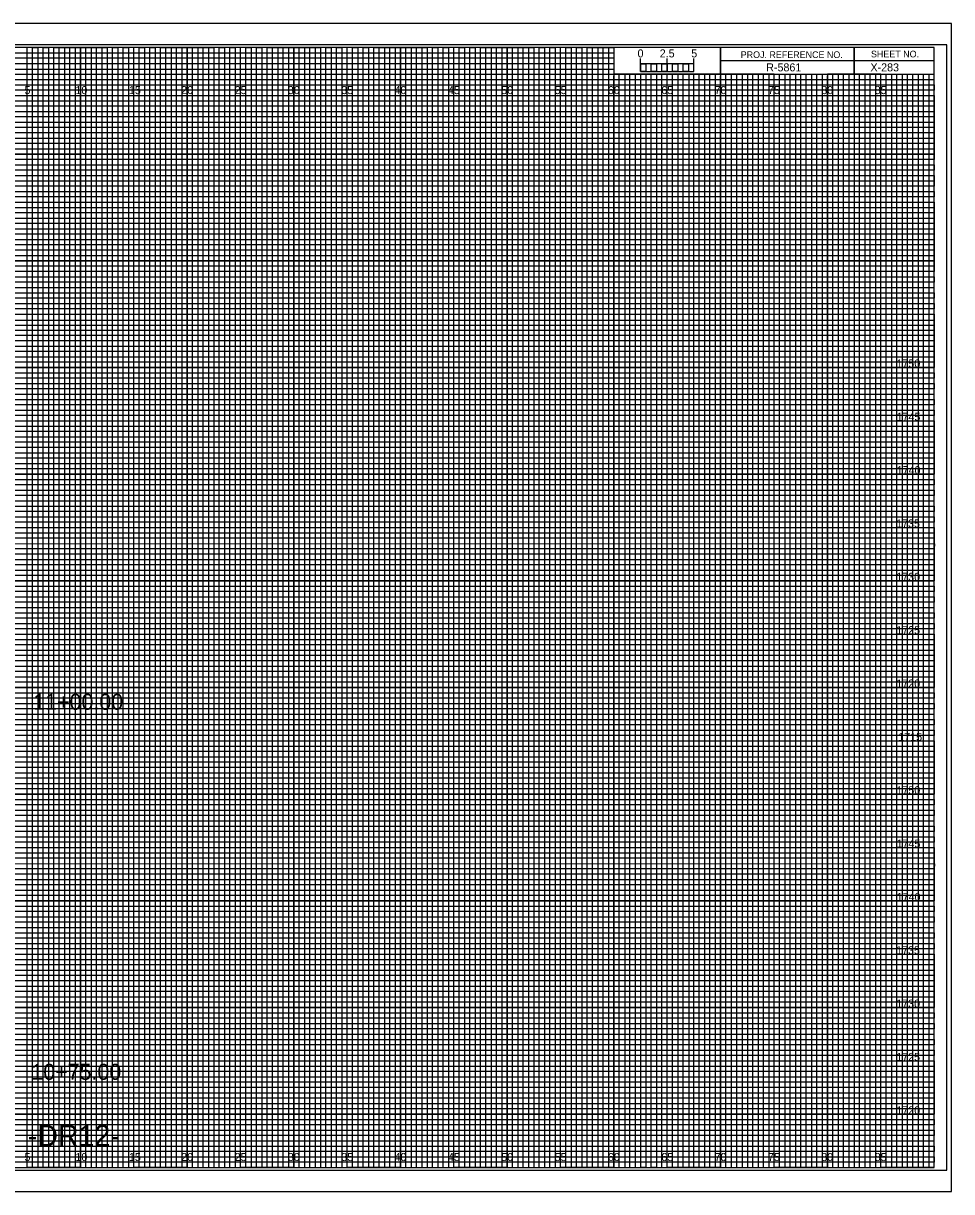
# Model space of a CAD drawing. Extents: x -7 to 162, y -2 to 327.
# Drawn here: x 74.6 to 161.7, y 107.7 to 217.2 of the extents above; entities that cross this region are included whole.
import ezdxf

# ---------------------------------------------------------------- set-up
doc = ezdxf.new("R2010")
doc.units = 0
for name, color, linetype in [('Prop XS Alignment Label', 7, 'Continuous'), ('Prop XS Bar Scale Labels', 7, 'Continuous'), ('Prop XS Elevation Labels', 7, 'Continuous'), ('Prop XS Offset Labels', 7, 'Continuous'), ('Prop XS Project Number', 7, 'Continuous'), ('Prop XS Sheet Number', 7, 'Continuous'), ('Prop XS Station Labels', 7, 'Continuous'), ('Sheet Cross Section CELL', 7, 'Continuous'), ('Sheet Cross Section Grid Major CELL', 7, 'Continuous'), ('Sheet Cross Section Grid Middle CELL', 7, 'Continuous'), ('Sheet Cross Section Grid Minor 1 CELL', 7, 'Continuous'), ('Sheet Cross Section Grid Minor 2 CELL', 7, 'Continuous'), ('Sheet Cross Section Scale CELL', 7, 'Continuous'), ('Sheet Cutting Line CELL', 7, 'Continuous'), ('Sheet DOT Grid CELL', 7, 'Continuous'), ('Sheet Plot Border Inside CELL', 7, 'Continuous'), ('Sheet Plot Border Outside CELL', 7, 'Continuous')]:
    doc.layers.add(name, color=color, linetype=linetype)

msp = doc.modelspace()

# ---------------------------------------------------------------- linework, layer by layer
at = {"layer": 'Sheet Cross Section CELL'}
for p, q in [((152.5, 215), (152.5, 212.5)), ((152.5, 212.5), (152.5, 215)), ((160, 213.75), (140, 213.75)), ((140, 213.75), (140, 212.5)), ((140, 212.5), (160, 212.5))]:
    msp.add_line(p, q, dxfattribs=at)
for points in [[(160, 215), (0, 215), (0, 110), (160, 110)], [(140, 215), (130, 215), (130, 212.52), (140, 212.52)], [(160, 215), (140, 215), (140, 212.5), (160, 212.5)]]:
    msp.add_lwpolyline(points, close=True, dxfattribs=at)
at = {"layer": 'Sheet Cross Section Grid Major CELL'}
for p, q in [((75, 215), (70, 215)), ((75, 110), (75, 215)), ((85, 215), (80, 215)), ((80, 215), (80, 110)), ((85, 110), (85, 215)), ((95, 215), (90, 215)), ((90, 215), (90, 110)), ((95, 110), (95, 215)), ((105, 215), (100, 215)), ((100, 215), (100, 110)), ((105, 110), (105, 215)), ((115, 215), (110, 215)), ((110, 215), (110, 110)), ((115, 110), (115, 215)), ((125, 215), (120, 215)), ((120, 215), (120, 110)), ((125, 110), (125, 215)), ((130, 215), (130, 110)), ((135, 110), (135, 212.5)), ((145, 212.5), (140, 212.5)), ((140, 212.5), (140, 110)), ((145, 110), (145, 212.5)), ((155, 212.5), (150, 212.5)), ((150, 212.5), (150, 110)), ((155, 110), (155, 212.5)), ((80, 110), (75, 110)), ((90, 110), (85, 110)), ((100, 110), (95, 110)), ((110, 110), (105, 110)), ((120, 110), (115, 110)), ((130, 110), (125, 110)), ((140, 110), (135, 110)), ((150, 110), (145, 110)), ((160, 110), (155, 110)), ((160, 110), (160, 110))]:
    msp.add_line(p, q, dxfattribs=at)
for points in [[(0, 210), (160, 210), (160, 205), (0, 205)], [(0, 200), (160, 200), (160, 195), (0, 195)], [(0, 190), (160, 190), (160, 185), (0, 185)], [(0, 180), (160, 180), (160, 175), (0, 175)], [(0, 170), (160, 170), (160, 165), (0, 165)], [(0, 160), (160, 160), (160, 155), (0, 155)], [(0, 150), (160, 150), (160, 145), (0, 145)], [(0, 140), (160, 140), (160, 135), (0, 135)], [(0, 130), (160, 130), (160, 125), (0, 125)], [(0, 120), (160, 120), (160, 115), (0, 115)]]:
    msp.add_lwpolyline(points, dxfattribs=at)
at = {"layer": 'Sheet Cross Section Grid Middle CELL'}
for points in [[(72.5, 110), (77.5, 110), (77.5, 215), (82.5, 215), (82.5, 110), (87.5, 110), (87.5, 215), (92.5, 215), (92.5, 110), (97.5, 110), (97.5, 215), (102.5, 215), (102.5, 110), (107.5, 110), (107.5, 215), (112.5, 215), (112.5, 110), (117.5, 110), (117.5, 215), (122.5, 215), (122.5, 110), (127.5, 110), (127.5, 215), (129.97, 215), (130, 215), (130, 212.5), (132.5, 212.5), (132.5, 110), (137.5, 110), (137.5, 212.5), (142.5, 212.5), (142.5, 110), (147.5, 110), (147.5, 212.5), (152.5, 212.5), (152.5, 110), (157.5, 110), (157.5, 212.5)], [(0, 212.5), (137.5, 212.5)], [(0, 202.5), (160, 202.5), (160, 207.5), (0, 207.5)], [(0, 192.5), (160, 192.5), (160, 197.5), (0, 197.5)], [(0, 182.5), (160, 182.5), (160, 187.5), (0, 187.5)], [(0, 172.5), (160, 172.5), (160, 177.5), (0, 177.5)], [(0, 162.5), (160, 162.5), (160, 167.5), (0, 167.5)], [(0, 152.5), (160, 152.5), (160, 157.5), (0, 157.5)], [(0, 142.5), (160, 142.5), (160, 147.5), (0, 147.5)], [(0, 132.5), (160, 132.5), (160, 137.5), (0, 137.5)], [(0, 122.5), (160, 122.5), (160, 127.5), (0, 127.5)], [(0, 112.5), (160, 112.5), (160, 117.5), (0, 117.5)]]:
    msp.add_lwpolyline(points, dxfattribs=at)
at = {"layer": 'Sheet Cross Section Grid Minor 1 CELL'}
for p, q in [((0, 214.5), (130, 214.5)), ((130, 213.99), (0, 213.99)), ((130, 214.5), (130, 213.99)), ((0, 213.5), (130, 213.5)), ((130, 212.94), (0, 212.94)), ((130, 213.5), (130, 212.94)), ((0, 212), (160, 212))]:
    msp.add_line(p, q, dxfattribs=at)
for points in [[(0, 211.5), (135, 211.5), (160, 211.5), (160, 211), (0, 211)], [(0, 210.5), (160, 210.5), (160, 209.5), (0, 209.5)], [(0, 209), (160, 209), (160, 208.5), (0, 208.49)], [(0, 208), (160, 208), (160, 207), (0, 207)], [(0, 206.5), (160, 206.5), (160, 206), (0, 206)], [(0, 205.5), (160, 205.5), (160, 204.5), (0, 204.5)], [(0, 204), (160, 204), (160, 203.5), (0, 203.5)], [(0, 203), (160, 203), (160, 202), (0, 202)], [(0, 201.5), (160, 201.5), (160, 201), (0, 201)], [(0, 200.5), (160, 200.5), (160, 199.5), (0, 199.5)], [(0, 199), (160, 199), (160, 198.5), (0, 198.5)], [(0, 198), (160, 198), (160, 196.97), (160, 196.5), (160, 196), (0, 196)], [(0, 197), (160, 197), (160, 196.5), (0, 196.5)], [(0, 195.5), (160, 195.5), (160, 194.5), (0, 194.52)], [(0, 194.52), (160, 194.5), (160, 194), (0, 194)], [(0, 193.5), (160, 193.5), (160, 193), (0, 193)], [(0, 192), (160, 192), (160, 191.5), (0, 191.5)], [(0, 191), (160, 191), (160, 190.5), (0, 190.5)], [(-0.04, 189.44), (160, 189.44), (160, 188.94), (-0.04, 188.94)], [(0, 188.5), (160, 188.5), (160, 188), (0, 188)], [(0, 187), (160, 187), (160, 186.5), (0, 186.5)], [(0, 186), (160, 186), (160, 185.5), (0, 185.5)], [(0, 184.5), (160, 184.5), (160, 184), (0, 184)], [(0, 183.5), (160, 183.5), (160, 183), (0, 183)], [(0, 182), (160, 182), (160, 181.5), (0, 181.5)], [(0, 181), (160, 181), (160, 180.5), (0, 180.5)], [(0, 179.5), (160, 179.5), (160, 178.99), (0, 179)], [(0, 178.5), (160, 178.5), (160, 178), (0, 178)], [(0, 177), (160, 177), (160, 176.5), (0, 176.5)], [(0, 176), (160, 176), (160, 175.5), (0, 175.5)], [(0, 174.5), (160, 174.5), (160, 174), (0, 174)], [(0, 173.5), (160, 173.5), (160, 173), (0, 173)], [(0, 172), (160, 172), (160, 171.5), (0, 171.5)], [(0, 171), (160, 171), (160, 170.5), (0, 170.5)], [(0, 169.5), (160, 169.5), (160, 169), (0, 169)], [(0, 168.5), (160.03, 168.46), (160, 168), (0, 168)], [(0, 167), (160, 167), (160, 166.5), (0, 166.5)], [(0, 166), (160, 166), (160, 165.5), (0, 165.5)], [(0, 164.5), (160, 164.5), (160, 164), (0, 164)], [(0, 163.5), (160, 163.5), (160, 163), (0, 163)], [(0, 162), (160, 162), (160, 161.5), (0, 161.5)], [(0, 161), (160, 161), (160, 160.5), (0, 160.5)], [(0, 159.5), (160, 159.5), (160, 159), (0, 159)], [(0, 158.5), (160, 158.5), (160, 158), (0, 158)], [(0, 157), (160, 157), (160, 156.5), (0, 156.5)], [(0, 156), (160, 156), (160, 155.5), (0, 155.5)], [(0, 154.5), (160, 154.5), (160, 154), (0, 154)], [(0, 153.5), (160, 153.5), (160, 153), (0, 153)], [(0, 152), (160, 152), (160, 151.5), (0, 151.5)], [(0, 151), (160, 151), (160, 150.5), (0, 150.5)], [(0, 149.5), (160, 149.5), (160, 148.99), (0, 149)], [(0, 148.5), (160, 148.5), (160, 148), (0, 148)], [(0, 147), (160, 147), (160, 146.5), (0, 146.5)], [(0, 146), (160, 146), (160, 145.5), (0, 145.5)], [(0, 144.5), (160, 144.5), (160, 144), (0, 144)], [(0, 143.5), (160, 143.5), (160, 143), (0, 143)], [(0, 142), (160, 142), (160, 141.5), (0, 141.5)], [(0, 141), (160, 141), (160, 140.5), (0, 140.5)], [(0, 139.5), (160, 139.5), (160, 139), (0, 139)], [(0, 138.5), (160.03, 138.46), (160, 138), (0, 138)], [(0, 137), (160, 137), (160, 136.5), (0, 136.5)], [(0, 136), (160, 136), (160, 135.5), (0, 135.5)], [(0, 134.5), (160, 134.5), (160, 134), (0, 134)], [(0, 133.5), (160, 133.5), (160, 133), (0, 133)], [(0, 132), (160, 132), (160, 131.5), (0, 131.5)], [(0, 131), (160, 131), (160, 130.5), (0, 130.5)], [(0, 129.5), (160, 129.5), (160, 129), (0, 129)], [(0, 128.5), (160, 128.5), (160, 128), (0, 128)], [(0, 127), (160, 127), (160, 126.5), (0, 126.5)], [(0, 126), (160, 126), (160, 125.5), (0, 125.5)], [(0, 124.5), (160, 124.5), (160, 124), (0, 124)], [(0, 123.5), (160, 123.5), (160, 123), (0, 123)], [(0, 122), (160, 122), (160, 121.5), (0, 121.5)], [(0, 121), (160, 121), (160, 120.5), (0, 120.5)], [(0, 119.5), (160, 119.5), (160, 119), (0, 119)], [(0, 118.5), (160, 118.5), (160, 118), (0, 118)], [(0, 117), (160, 117), (160, 116.5), (0, 116.5)], [(0, 116), (160, 116), (160, 115.5), (0, 115.5)], [(0, 114.5), (160, 114.5), (160, 114), (0, 114)], [(0, 113.5), (160, 113.5), (160, 113), (0, 113)], [(0, 112), (160, 112), (160, 111.5), (0, 111.5)], [(0, 111), (160, 111), (160, 110.5), (0, 110.5)]]:
    msp.add_lwpolyline(points, dxfattribs=at)
at = {"layer": 'Sheet Cross Section Grid Minor 2 CELL'}
for p, q in [((133.5, 212.5), (133, 212.5)), ((133, 212.5), (133, 110)), ((133.5, 110), (133.5, 212.5)), ((134.5, 212.5), (134, 212.5)), ((134, 212.5), (134, 110)), ((134.5, 110), (134.5, 212.5)), ((133, 110), (132.5, 110)), ((134, 110), (133.5, 110))]:
    msp.add_line(p, q, dxfattribs=at)
for points in [[(75, 110), (75.5, 110), (75.5, 215), (76, 215), (76, 110)], [(76, 110), (76.5, 110), (76.5, 215), (77, 215), (77, 110)], [(77.5, 110), (78, 110), (78, 215), (78.5, 215), (78.5, 110)], [(78.5, 110), (79, 110), (79, 215), (79.5, 215), (79.5, 110)], [(80, 110), (80.5, 110), (80.5, 215), (81, 215), (81, 110)], [(81, 110), (81.5, 110), (81.5, 215), (82, 215), (82, 110)], [(82.5, 110), (83, 110), (83, 215), (83.5, 215), (83.5, 110)], [(83.5, 110), (84, 110), (84, 215), (84.5, 215), (84.5, 110)], [(85, 110), (85.5, 110), (85.5, 215), (86, 215), (86, 110)], [(86, 110), (86.5, 110), (86.5, 215), (87, 215), (87, 110)], [(87.5, 110), (88, 110), (88, 215), (88.5, 215), (88.5, 110)], [(88.5, 110), (89, 110), (89, 215), (89.5, 215), (89.5, 110)], [(90, 110), (90.5, 110), (90.5, 215), (91, 215), (91, 110)], [(91, 110), (91.5, 110), (91.5, 215), (92, 215), (92, 110)], [(92.5, 110), (93, 110), (93, 215), (93.5, 215), (93.5, 110)], [(93.5, 110), (94, 110), (94, 215), (94.5, 215), (94.5, 110)], [(95, 110), (95.5, 110), (95.5, 215), (96, 215), (96, 110)], [(96, 110), (96.5, 110), (96.5, 215), (97, 215), (97, 110)], [(97.5, 110), (98, 110), (98, 215), (98.5, 215), (98.5, 110)], [(98.5, 110), (99, 110), (99, 215), (99.5, 215), (99.5, 110)], [(100, 110), (100.5, 110), (100.5, 215), (101, 215), (101, 110)], [(101, 110), (101.5, 110), (101.5, 215), (102, 215), (102, 110)], [(102.5, 110), (103, 110), (103, 215), (103.5, 215), (103.5, 110)], [(103.5, 110), (104, 110), (104, 215), (104.5, 215), (104.5, 110)], [(105, 110), (105.5, 110), (105.5, 215), (106, 215), (106, 110)], [(106, 110), (106.5, 110), (106.5, 215), (107, 215), (107, 110)], [(107.5, 110), (108, 110), (108, 215), (108.5, 215), (108.5, 110)], [(108.5, 110), (109, 110), (109, 215), (109.5, 215), (109.5, 110)], [(110, 110), (110.5, 110), (110.5, 215), (111, 215), (111, 110)], [(111, 110), (111.5, 110), (111.5, 215), (112, 215), (112, 110)], [(112.5, 110), (113, 110), (113, 215), (113.5, 215), (113.5, 110)], [(113.5, 110), (114, 110), (114, 215), (114.5, 215), (114.5, 110)], [(115, 110), (115.5, 110), (115.5, 215), (116, 215), (116, 110)], [(116, 110), (116.5, 110), (116.5, 215), (117, 215), (117, 110)], [(117.5, 110), (118, 110), (118, 215), (118.5, 215), (118.5, 110)], [(118.5, 110), (119, 110), (119, 215), (119.5, 215), (119.5, 110)], [(120, 110), (120.5, 110), (120.5, 215), (121, 215), (121, 110)], [(121, 110), (121.5, 110), (121.5, 215), (122, 215), (122, 110)], [(122.5, 110), (123, 110), (123, 215), (123.5, 215), (123.5, 110)], [(123.5, 110), (124, 110), (124, 215), (124.5, 215), (124.5, 110)], [(125, 110), (125.5, 110), (125.5, 215), (126, 215), (126, 110)], [(126, 110), (126.5, 110), (126.5, 215), (127, 215), (127, 110)], [(127.5, 110), (128, 110), (128, 215), (128.5, 215), (128.5, 110)], [(128.5, 110), (129, 110), (129, 215), (129.5, 215), (129.5, 110)], [(130, 110), (130.5, 110), (130.5, 212.5), (131.01, 212.5), (131.01, 110)], [(131, 110), (131.5, 110), (131.5, 212.5), (132, 212.5), (132, 110)], [(135, 110), (135.49, 110), (135.49, 212.5), (136, 212.5), (136, 110)], [(136, 110), (136.5, 110), (136.5, 212.5), (137.03, 212.5), (137.03, 110)], [(137.5, 110), (138, 110), (138, 212.5), (138.5, 212.5), (138.5, 110)], [(138.5, 110), (139, 110), (139, 212.5), (139.5, 212.5), (139.5, 110)], [(140, 110), (140.5, 110), (140.5, 212.5), (141, 212.5), (141, 110)], [(141, 110), (141.5, 110), (141.5, 212.5), (142, 212.5), (142, 110)], [(142.5, 110), (143, 110), (143, 212.5), (143.5, 212.5), (143.5, 110)], [(143.5, 110), (144, 110), (144, 212.5), (144.5, 212.5), (144.5, 110)], [(145, 110), (145.5, 110), (145.5, 212.5), (146, 212.5), (146, 110)], [(146, 110), (146.5, 110), (146.5, 212.5), (147, 212.5), (147, 110)], [(147.5, 110), (148, 110), (148, 212.5), (148.5, 212.5), (148.5, 110)], [(148.5, 110), (149, 110), (149, 212.5), (149.5, 212.5), (149.5, 110)], [(150, 110), (150.5, 110), (150.5, 212.5), (151, 212.5), (151, 110)], [(151, 110), (151.5, 110), (151.5, 212.5), (152, 212.5), (152, 110)], [(152.5, 110), (153, 110), (153, 212.5), (153.5, 212.5), (153.5, 110)], [(153.5, 110), (154, 110), (154, 212.5), (154.5, 212.5), (154.5, 110)], [(155, 110), (155.5, 110), (155.5, 212.5), (156, 212.5), (156, 110)], [(156, 110), (156.5, 110), (156.5, 212.5), (157, 212.5), (157, 110)], [(157.5, 110), (158, 110), (158, 212.5), (158.5, 212.5), (158.5, 110)], [(158.5, 110), (159, 110), (159, 212.5), (159.5, 212.5), (159.5, 110)]]:
    msp.add_lwpolyline(points, dxfattribs=at)
at = {"layer": 'Sheet Cross Section Scale CELL'}
for p, q in [((132.5, 212.75), (132.5, 213.95)), ((132.5, 213.45), (132.5, 213.95)), ((135, 212.75), (135, 213.95)), ((137.5, 212.75), (137.5, 213.95)), ((137.5, 213.45), (137.5, 213.95))]:
    msp.add_line(p, q, dxfattribs=at)
for points in [[(137.5, 213.45), (132.5, 213.45), (132.5, 212.75), (137.5, 212.75)], [(132.5, 213.45), (133, 213.45), (133, 212.75), (132.5, 212.75)], [(133.5, 213.45), (134, 213.45), (134, 212.75), (133.5, 212.75)], [(134.5, 213.45), (135, 213.45), (135, 212.75), (134.5, 212.75)], [(135.5, 213.45), (136, 213.45), (136, 212.75), (135.5, 212.75)], [(136.5, 213.45), (137, 213.45), (137, 212.75), (136.5, 212.75)]]:
    msp.add_lwpolyline(points, close=True, dxfattribs=at)
at = {"layer": 'Sheet Cutting Line CELL'}
for p, q in [((161.65, 217.25), (-6.7, 217.25)), ((-6.7, 107.75), (161.65, 107.75))]:
    msp.add_line(p, q, dxfattribs=at)
at = {"layer": 'Sheet DOT Grid CELL'}
for p, q in [((75, 110), (75, 215)), ((80, 110), (80, 215)), ((85, 110), (85, 215)), ((90, 110), (90, 215)), ((95, 110), (95, 215)), ((100, 110), (100, 215)), ((105, 110), (105, 215)), ((110, 110), (110, 215)), ((115, 110), (115, 215)), ((120, 110), (120, 215)), ((125, 110), (125, 215)), ((130, 110), (130, 212.34)), ((135, 110), (135, 212.34)), ((140, 110), (140, 212.34)), ((145, 110), (145, 212.34)), ((150, 110), (150, 212.34)), ((155, 110), (155, 212.34)), ((0, 210), (160, 210)), ((0, 205), (160, 205)), ((0, 200), (160, 200)), ((0, 195), (160, 195)), ((0, 190), (160, 190)), ((0, 185), (160, 185)), ((0, 180), (160, 180)), ((0, 175), (160, 175)), ((0, 170), (160, 170)), ((0, 165), (160, 165)), ((0, 160), (160, 160)), ((0, 155), (160, 155)), ((0, 150), (160, 150)), ((0, 145), (160, 145)), ((0, 140), (160, 140)), ((0, 135), (160, 135)), ((0, 130), (160, 130)), ((0, 125), (160, 125)), ((0, 120), (160, 120)), ((0, 115), (160, 115))]:
    msp.add_line(p, q, dxfattribs=at)
at = {"layer": 'Sheet Plot Border Inside CELL'}
msp.add_lwpolyline([(-5.4, 109.75), (161.2, 109.75), (161.2, 215.25), (-5.4, 215.25)], close=True, dxfattribs=at)
at = {"layer": 'Sheet Plot Border Outside CELL'}
msp.add_lwpolyline([(-6.7, 107.75), (161.65, 107.75), (161.65, 217.25), (-6.7, 217.25)], close=True, dxfattribs=at)

# ---------------------------------------------------------------- texts
at = {"layer": 'Prop XS Alignment Label'}
msp.add_text('-DR12-', height=2, dxfattribs=at).set_placement((75.06, 112))
at = {"layer": 'Prop XS Bar Scale Labels'}
for s, p in [('2.5', (134.29, 214.06)), ('5', (137.24, 214.06))]:
    msp.add_text(s, height=0.75, dxfattribs=at).set_placement(p)
at = {"layer": 'Prop XS Elevation Labels'}
for s, p in [('1750', (156.48, 185)), ('1745', (156.49, 180)), ('1740', (156.5, 175)), ('1735', (156.45, 170)), ('1730', (156.46, 165)), ('1725', (156.46, 160)), ('1720', (156.47, 155)), ('1715', (156.65, 150)), ('1750', (156.48, 145)), ('1745', (156.49, 140)), ('1740', (156.5, 135)), ('1735', (156.45, 130)), ('1730', (156.46, 125)), ('1725', (156.46, 120)), ('1720', (156.47, 115))]:
    msp.add_text(s, height=0.75, dxfattribs=at).set_placement(p)
at = {"layer": 'Prop XS Offset Labels'}
for s, p in [('5', (74.74, 210.62)), ('10', (79.52, 210.62)), ('15', (84.53, 210.62)), ('20', (89.43, 210.62)), ('25', (94.44, 210.62)), ('30', (99.43, 210.62)), ('35', (104.44, 210.62)), ('40', (109.43, 210.62)), ('45', (114.44, 210.62)), ('50', (119.43, 210.62)), ('55', (124.44, 210.62)), ('60', (129.43, 210.62)), ('65', (134.44, 210.62)), ('70', (139.43, 210.62)), ('75', (144.44, 210.62)), ('80', (149.43, 210.62)), ('85', (154.44, 210.62)), ('5', (74.74, 110.62)), ('10', (79.52, 110.62)), ('15', (84.53, 110.62)), ('20', (89.43, 110.62)), ('25', (94.44, 110.62)), ('30', (99.43, 110.62)), ('35', (104.44, 110.62)), ('40', (109.43, 110.62)), ('45', (114.44, 110.62)), ('50', (119.43, 110.62)), ('55', (124.44, 110.62)), ('60', (129.43, 110.62)), ('65', (134.44, 110.62)), ('70', (139.43, 110.62)), ('75', (144.44, 110.62)), ('80', (149.43, 110.62)), ('85', (154.44, 110.62))]:
    msp.add_text(s, height=0.75, dxfattribs=at).set_placement(p)
at = {"layer": 'Prop XS Project Number'}
msp.add_text('R-5861', height=0.75, dxfattribs=at).set_placement((144.27, 212.75))
at = {"layer": 'Prop XS Sheet Number'}
msp.add_text('X-283', height=0.75, dxfattribs=at).set_placement((154.04, 212.75))
at = {"layer": 'Prop XS Station Labels'}
for s, p in [('11+00.00', (75.57, 152.91)), ('10+75.00', (75.39, 118.23))]:
    msp.add_text(s, height=1.5, dxfattribs=at).set_placement(p)
at = {"layer": 'Sheet Cross Section CELL'}
for s, p in [('PROJ. REFERENCE NO.', (141.88, 214)), ('SHEET NO.', (154.09, 214.06))]:
    msp.add_text(s, height=0.625, dxfattribs=at).set_placement(p)
at = {"layer": 'Sheet Cross Section Scale CELL'}
msp.add_text('0', height=0.75, dxfattribs=at).set_placement((132.21, 214.06))

doc.saveas('drawing.dxf')
